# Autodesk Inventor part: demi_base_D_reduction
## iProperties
Shininess: 64.0
Length Units: 11269
Angle Units: 11279
Time Units: 11290
Mass Units: 11283
Length Display Precision: 3
Angle Display Precision: 2
Compacted: True
Part Number: demi_base_D_reduction
Document SubType Name: Modeling
Created: 2008-02
Material: Acier doux
Designer: Pascal
Density: 7.86 g/cm^3
Density: 0.0
Volumn: 0.0
Area: 0.0
PropertySet Name: Model Information
Control State: 0
Master: False
Checked Out: False
MATIERE_PIECE: X2CrNi 18-11
OBSERVATIONS: Tôle ep. 15/10
DESIGNATION: Demi-réduction droite
Author: Pascal
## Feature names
1. Lissage1
2. Coque1
3. Extrusion1
